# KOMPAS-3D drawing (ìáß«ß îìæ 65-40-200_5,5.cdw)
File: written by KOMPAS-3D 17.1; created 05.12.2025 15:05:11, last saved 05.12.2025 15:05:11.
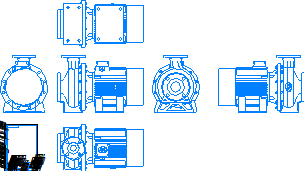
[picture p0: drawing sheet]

Sheet 1: A4, portrait

Title block, sheet 1: name: Насос МНС / 65-40-200_5,5; material: Сталь 10  ГОСТ 1050-88; mass: 165,61; sheets: 1; sheet format: A4

Views: Вид 1, Спереди, Проекционный вид 2, Проекционный вид 3, Проекционный вид 4, Проекционный вид 6
Referenced files in \\adlc.lan\data\АДЛ_ПКД\3D-модели\ADL production\Насосы ГРАНПАМП\Насосы ГРАНПАМП серии МНС\KOMPAS 3D\: Насос МНС 65-40-200_5,5.m3d
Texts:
  Andrey
  АДЛ
Dimensions and other numbers on the sheet: 1:1; 1; 65-40-200_5,5; 165,61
